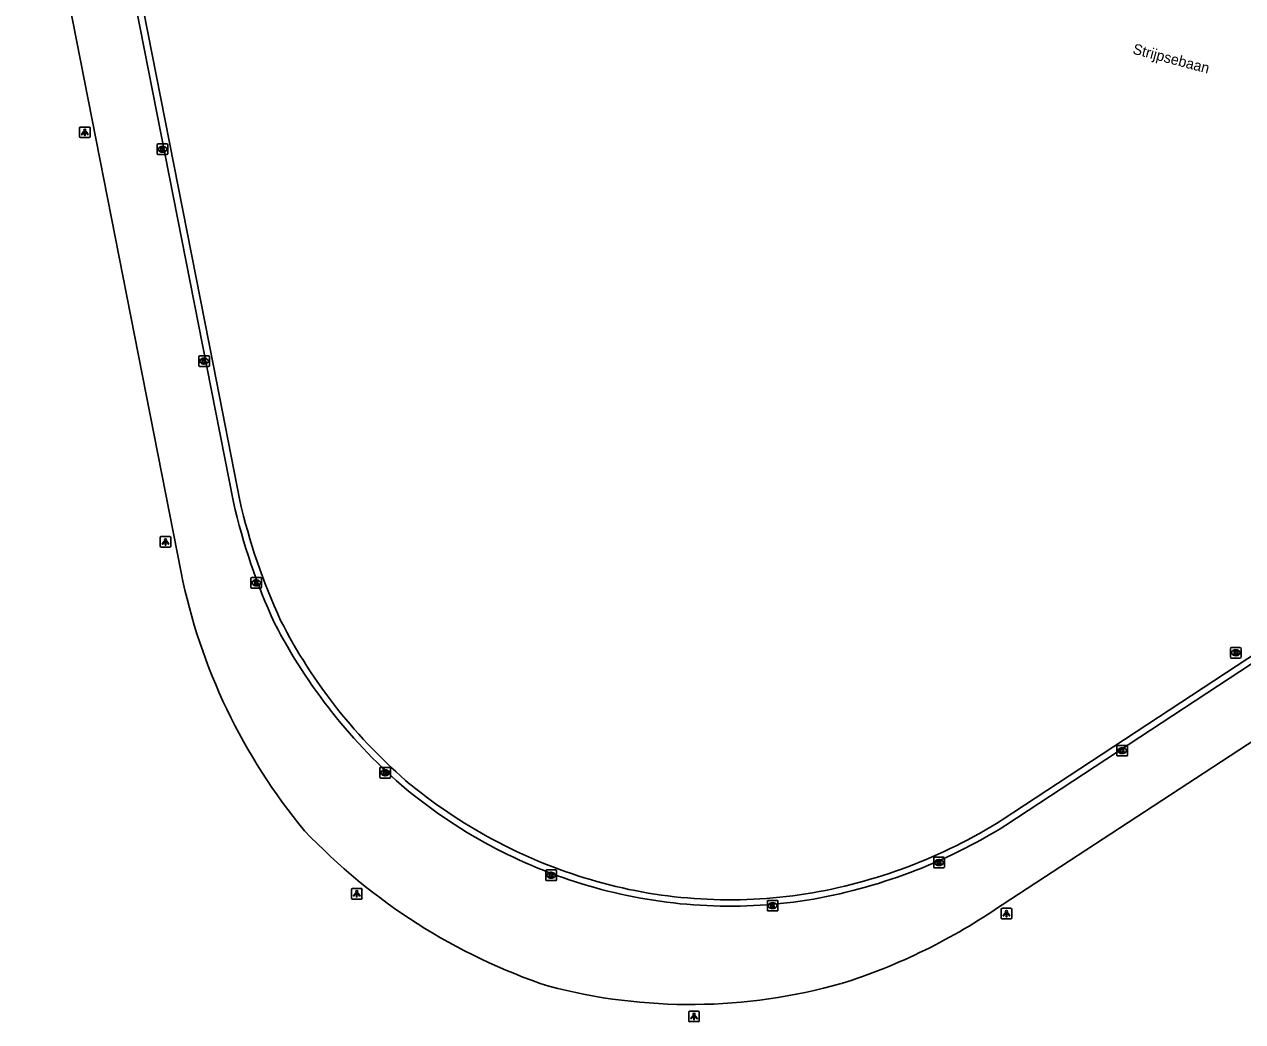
# Model space of a CAD drawing. Extents: x 154324 to 155743, y 382939 to 384183.
# Drawn here: x 154446.7 to 154562, y 382939 to 383033.4 of the extents above; entities that cross this region are included whole.
import ezdxf

# ---------------------------------------------------------------- set-up
doc = ezdxf.new("R2010")
doc.units = 0
for name, color, linetype in [('IMGEO_Brandkraan', 7, 'Continuous'), ('IMGEO_Kolk', 7, 'Continuous'), ('IMGEO_Lichtpunt', 7, 'Continuous'), ('IMGEO_Openbare_ruimte_label', 7, 'Continuous'), ('IMGEO_Rijbaan_lokaal_gesloten', 7, 'Continuous')]:
    doc.layers.add(name, color=color, linetype=linetype)

msp = doc.modelspace()

# ---------------------------------------------------------------- linework, layer by layer
at = {"layer": 'IMGEO_Brandkraan'}
for p, q in [((154560.89, 382973.52), (154560.89, 382974.37)), ((154560.96, 382974.45), (154561.81, 382974.45)), ((154561.81, 382973.45), (154560.96, 382973.45)), ((154561.37, 382974.23), (154561.4, 382974.23)), ((154561.4, 382973.67), (154561.37, 382973.67)), ((154561.89, 382974.37), (154561.89, 382973.52))]:
    msp.add_line(p, q, dxfattribs=at)
for points in [[(154560.89, 382973.52), (154560.89, 382974.37)], [(154560.96, 382974.45), (154561.81, 382974.45)], [(154561.81, 382973.45), (154560.96, 382973.45)], [(154561.23, 382974.15), (154561.23, 382973.75), (154561.45, 382973.75)], [(154561.47, 382974.15), (154561.23, 382974.15)], [(154561.41, 382974.07), (154561.36, 382974.07), (154561.36, 382973.99)], [(154561.36, 382973.99), (154561.41, 382973.99)], [(154561.42, 382973.91), (154561.36, 382973.91), (154561.36, 382973.83)], [(154561.36, 382973.83), (154561.42, 382973.83)], [(154561.89, 382974.37), (154561.89, 382973.52)]]:
    msp.add_lwpolyline(points, dxfattribs=at)
for centre, radius, start, end in [((154560.96, 382974.37), 0.0765, 91.552, 178.448), ((154560.96, 382974.37), 0.0765, 91.552, 178.448), ((154560.96, 382973.52), 0.0765, 181.552, 268.448), ((154560.96, 382973.52), 0.0765, 181.552, 268.448), ((154561.41, 382974.03), 0.0379, 267.8285, 90.9355), ((154561.42, 382973.87), 0.0404, 269.8759, 90.5077), ((154561.45, 382974), 0.251, 268.6676, 293.5347), ((154561.47, 382974), 0.145, 59.4692, 91.5367), ((154561.49, 382974.05), 0.0922, 285.5137, 58.1501), ((154561.5, 382973.86), 0.105, 301.3115, 78.989), ((154561.81, 382974.37), 0.0765, 1.552, 88.448), ((154561.81, 382974.37), 0.0765, 1.552, 88.448), ((154561.81, 382973.52), 0.0765, 271.552, 358.448), ((154561.81, 382973.52), 0.0765, 271.552, 358.448)]:
    msp.add_arc(centre, radius, start, end, dxfattribs=at)
for centre, major_axis, ratio, start_param, end_param in [((154561.37, 382973.95), (-0.387, 0.002), 0.722429, 4.712389, 7.853982), ((154561.4, 382973.95), (-0.39, 0.002), 0.717154, 1.570796, 4.712389)]:
    msp.add_ellipse(centre, major_axis=major_axis, ratio=ratio, start_param=start_param, end_param=end_param, dxfattribs=at)
at = {"layer": 'IMGEO_Kolk'}
for p, q in [((154459.24, 383021.2), (154459.24, 383022.05)), ((154459.31, 383022.12), (154460.17, 383022.12)), ((154459.73, 383021.9), (154459.75, 383021.9)), ((154460.24, 383022.05), (154460.24, 383021.2)), ((154460.17, 383021.12), (154459.31, 383021.12)), ((154459.75, 383021.34), (154459.72, 383021.34)), ((154463.18, 383001.14), (154463.18, 383001.99)), ((154463.26, 383002.06), (154464.11, 383002.06)), ((154464.11, 383001.06), (154463.26, 383001.06)), ((154463.67, 383001.84), (154463.7, 383001.84)), ((154463.69, 383001.28), (154463.67, 383001.28)), ((154464.19, 383001.99), (154464.19, 383001.14)), ((154468.12, 382980.15), (154468.12, 382981)), ((154468.19, 382981.08), (154469.05, 382981.08)), ((154468.63, 382980.3), (154468.6, 382980.3)), ((154468.61, 382980.85), (154468.63, 382980.85)), ((154469.12, 382981), (154469.12, 382980.15)), ((154469.05, 382980.07), (154468.19, 382980.07)), ((154550.12, 382964.25), (154550.12, 382965.11)), ((154550.2, 382965.18), (154551.05, 382965.18)), ((154551.05, 382964.18), (154550.2, 382964.18)), ((154550.61, 382964.96), (154550.63, 382964.96)), ((154550.63, 382964.4), (154550.61, 382964.4)), ((154551.12, 382965.11), (154551.12, 382964.25)), ((154480.32, 382962.17), (154480.32, 382963.02)), ((154480.4, 382963.09), (154481.25, 382963.09)), ((154481.32, 382963.02), (154481.32, 382962.17)), ((154481.25, 382962.09), (154480.4, 382962.09)), ((154480.81, 382962.87), (154480.84, 382962.87)), ((154480.83, 382962.31), (154480.81, 382962.31)), ((154532.78, 382953.66), (154532.78, 382954.52)), ((154532.85, 382954.59), (154533.7, 382954.59)), ((154533.26, 382954.37), (154533.29, 382954.37)), ((154533.29, 382953.81), (154533.26, 382953.81)), ((154533.78, 382954.52), (154533.78, 382953.66)), ((154496.04, 382952.46), (154496.04, 382953.31)), ((154496.12, 382953.39), (154496.97, 382953.39)), ((154496.53, 382953.17), (154496.56, 382953.17)), ((154496.55, 382952.61), (154496.53, 382952.61)), ((154497.04, 382953.31), (154497.04, 382952.46)), ((154533.7, 382953.59), (154532.85, 382953.59)), ((154496.97, 382952.39), (154496.12, 382952.39)), ((154517.02, 382949.58), (154517.02, 382950.43)), ((154517.1, 382950.51), (154517.95, 382950.51)), ((154517.51, 382950.29), (154517.53, 382950.29)), ((154518.02, 382950.43), (154518.02, 382949.58)), ((154517.95, 382949.51), (154517.1, 382949.51)), ((154517.53, 382949.73), (154517.51, 382949.73))]:
    msp.add_line(p, q, dxfattribs=at)
for points in [[(154459.24, 383021.2), (154459.24, 383022.05)], [(154459.31, 383022.12), (154460.17, 383022.12)], [(154459.56, 383021.82), (154459.68, 383021.82), (154459.68, 383021.67), (154459.81, 383021.82), (154459.98, 383021.82), (154459.83, 383021.67), (154459.98, 383021.42), (154459.83, 383021.42), (154459.75, 383021.59), (154459.68, 383021.52), (154459.68, 383021.42), (154459.56, 383021.42), (154459.56, 383021.82)], [(154460.24, 383022.05), (154460.24, 383021.2)], [(154460.17, 383021.12), (154459.31, 383021.12)], [(154463.18, 383001.14), (154463.18, 383001.99)], [(154463.26, 383002.06), (154464.11, 383002.06)], [(154464.11, 383001.06), (154463.26, 383001.06)], [(154463.5, 383001.76), (154463.63, 383001.76), (154463.63, 383001.61), (154463.76, 383001.76), (154463.92, 383001.76), (154463.78, 383001.61), (154463.93, 383001.36), (154463.78, 383001.36), (154463.69, 383001.53), (154463.63, 383001.46), (154463.63, 383001.36), (154463.5, 383001.36), (154463.5, 383001.76)], [(154464.19, 383001.99), (154464.19, 383001.14)], [(154468.12, 382980.15), (154468.12, 382981)], [(154468.19, 382981.08), (154469.05, 382981.08)], [(154468.44, 382980.77), (154468.56, 382980.77), (154468.56, 382980.62), (154468.69, 382980.77), (154468.86, 382980.77), (154468.71, 382980.62), (154468.86, 382980.37), (154468.71, 382980.37), (154468.63, 382980.54), (154468.56, 382980.47), (154468.56, 382980.37), (154468.44, 382980.37), (154468.44, 382980.77)], [(154469.12, 382981), (154469.12, 382980.15)], [(154469.05, 382980.07), (154468.19, 382980.07)], [(154550.12, 382964.25), (154550.12, 382965.11)], [(154550.2, 382965.18), (154551.05, 382965.18)], [(154551.05, 382964.18), (154550.2, 382964.18)], [(154550.44, 382964.88), (154550.57, 382964.88), (154550.57, 382964.73), (154550.69, 382964.88), (154550.86, 382964.88), (154550.71, 382964.73), (154550.87, 382964.48), (154550.71, 382964.48), (154550.63, 382964.64), (154550.57, 382964.58), (154550.57, 382964.48), (154550.44, 382964.48), (154550.44, 382964.88)], [(154551.12, 382965.11), (154551.12, 382964.25)], [(154480.32, 382962.17), (154480.32, 382963.02)], [(154480.4, 382963.09), (154481.25, 382963.09)], [(154481.32, 382963.02), (154481.32, 382962.17)], [(154481.25, 382962.09), (154480.4, 382962.09)], [(154480.64, 382962.79), (154480.77, 382962.79), (154480.77, 382962.64), (154480.9, 382962.79), (154481.06, 382962.79), (154480.91, 382962.64), (154481.07, 382962.39), (154480.91, 382962.39), (154480.83, 382962.56), (154480.77, 382962.49), (154480.77, 382962.39), (154480.64, 382962.39), (154480.64, 382962.79)], [(154532.78, 382953.66), (154532.78, 382954.52)], [(154532.85, 382954.59), (154533.7, 382954.59)], [(154533.1, 382954.29), (154533.22, 382954.29), (154533.22, 382954.14), (154533.35, 382954.29), (154533.51, 382954.29), (154533.37, 382954.14), (154533.52, 382953.89), (154533.37, 382953.89), (154533.28, 382954.06), (154533.22, 382953.99), (154533.22, 382953.89), (154533.1, 382953.89), (154533.1, 382954.29)], [(154533.78, 382954.52), (154533.78, 382953.66)], [(154496.04, 382952.46), (154496.04, 382953.31)], [(154496.12, 382953.39), (154496.97, 382953.39)], [(154496.36, 382953.09), (154496.49, 382953.09), (154496.49, 382952.94), (154496.62, 382953.09), (154496.78, 382953.09), (154496.63, 382952.94), (154496.79, 382952.69), (154496.63, 382952.69), (154496.55, 382952.85), (154496.49, 382952.79), (154496.49, 382952.69), (154496.36, 382952.69), (154496.36, 382953.09)], [(154497.04, 382953.31), (154497.04, 382952.46)], [(154533.7, 382953.59), (154532.85, 382953.59)], [(154496.97, 382952.39), (154496.12, 382952.39)], [(154517.02, 382949.58), (154517.02, 382950.43)], [(154517.1, 382950.51), (154517.95, 382950.51)], [(154518.02, 382950.43), (154518.02, 382949.58)], [(154517.95, 382949.51), (154517.1, 382949.51)], [(154517.34, 382950.21), (154517.47, 382950.21), (154517.47, 382950.05), (154517.59, 382950.21), (154517.76, 382950.21), (154517.61, 382950.06), (154517.77, 382949.81), (154517.61, 382949.81), (154517.53, 382949.97), (154517.47, 382949.9), (154517.47, 382949.81), (154517.34, 382949.81), (154517.34, 382950.21)]]:
    msp.add_lwpolyline(points, dxfattribs=at)
for centre, start, end in [((154459.31, 383022.05), 91.552, 178.448), ((154459.31, 383022.05), 91.552, 178.448), ((154460.16, 383022.05), 1.552, 88.448), ((154460.16, 383022.05), 1.552, 88.448), ((154459.31, 383021.2), 181.552, 268.448), ((154459.31, 383021.2), 181.552, 268.448), ((154460.16, 383021.2), 271.552, 358.448), ((154460.16, 383021.2), 271.552, 358.448), ((154463.26, 383001.99), 91.552, 178.448), ((154463.26, 383001.99), 91.552, 178.448), ((154463.26, 383001.14), 181.552, 268.448), ((154463.26, 383001.14), 181.552, 268.448), ((154464.11, 383001.99), 1.552, 88.448), ((154464.11, 383001.99), 1.552, 88.448), ((154464.11, 383001.14), 271.552, 358.448), ((154464.11, 383001.14), 271.552, 358.448), ((154468.19, 382981), 91.552, 178.448), ((154468.19, 382981), 91.552, 178.448), ((154469.04, 382981), 1.552, 88.448), ((154469.04, 382981), 1.552, 88.448), ((154468.19, 382980.15), 181.552, 268.448), ((154468.19, 382980.15), 181.552, 268.448), ((154469.04, 382980.15), 271.552, 358.448), ((154469.04, 382980.15), 271.552, 358.448), ((154550.2, 382965.1), 91.552, 178.448), ((154550.2, 382965.1), 91.552, 178.448), ((154550.2, 382964.26), 181.552, 268.448), ((154550.2, 382964.26), 181.552, 268.448), ((154551.05, 382965.1), 1.552, 88.448), ((154551.05, 382965.1), 1.552, 88.448), ((154551.05, 382964.26), 271.552, 358.448), ((154551.05, 382964.26), 271.552, 358.448), ((154480.4, 382963.02), 91.552, 178.448), ((154480.4, 382963.02), 91.552, 178.448), ((154481.25, 382963.02), 1.552, 88.448), ((154481.25, 382963.02), 1.552, 88.448), ((154480.4, 382962.17), 181.552, 268.448), ((154480.4, 382962.17), 181.552, 268.448), ((154481.25, 382962.17), 271.552, 358.448), ((154481.25, 382962.17), 271.552, 358.448), ((154532.85, 382954.52), 91.552, 178.448), ((154532.85, 382954.52), 91.552, 178.448), ((154533.7, 382954.52), 1.552, 88.448), ((154533.7, 382954.52), 1.552, 88.448), ((154496.12, 382953.31), 91.552, 178.448), ((154496.12, 382953.31), 91.552, 178.448), ((154496.97, 382953.31), 1.552, 88.448), ((154496.97, 382953.31), 1.552, 88.448), ((154532.85, 382953.67), 181.552, 268.448), ((154532.85, 382953.67), 181.552, 268.448), ((154533.7, 382953.67), 271.552, 358.448), ((154533.7, 382953.67), 271.552, 358.448), ((154496.12, 382952.46), 181.552, 268.448), ((154496.12, 382952.46), 181.552, 268.448), ((154496.97, 382952.46), 271.552, 358.448), ((154496.97, 382952.46), 271.552, 358.448), ((154517.1, 382950.43), 91.552, 178.448), ((154517.1, 382950.43), 91.552, 178.448), ((154517.95, 382950.43), 1.552, 88.448), ((154517.95, 382950.43), 1.552, 88.448), ((154517.1, 382949.58), 181.552, 268.448), ((154517.1, 382949.58), 181.552, 268.448), ((154517.95, 382949.58), 271.552, 358.448), ((154517.95, 382949.58), 271.552, 358.448)]:
    msp.add_arc(centre, 0.0765, start, end, dxfattribs=at)
for centre, major_axis, ratio, start_param, end_param in [((154459.73, 383021.62), (-0.387, 0.002), 0.722429, 4.712389, 7.853982), ((154459.75, 383021.62), (-0.39, 0.002), 0.717154, 1.570796, 4.712389), ((154463.67, 383001.56), (-0.387, 0.002), 0.722429, 4.712389, 7.853982), ((154463.7, 383001.56), (-0.39, 0.002), 0.717154, 1.570796, 4.712389), ((154468.61, 382980.57), (-0.387, 0.002), 0.722429, 4.712389, 7.853982), ((154468.63, 382980.57), (-0.39, 0.002), 0.717154, 1.570796, 4.712389), ((154550.61, 382964.68), (-0.387, 0.002), 0.722429, 4.712389, 7.853982), ((154550.63, 382964.68), (-0.39, 0.002), 0.717154, 1.570796, 4.712389), ((154480.81, 382962.59), (-0.387, 0.002), 0.722429, 4.712389, 7.853982), ((154480.83, 382962.59), (-0.39, 0.002), 0.717154, 1.570796, 4.712389), ((154533.26, 382954.09), (-0.387, 0.002), 0.722429, 4.712389, 7.853982), ((154533.29, 382954.09), (-0.39, 0.002), 0.717154, 1.570796, 4.712389), ((154496.53, 382952.89), (-0.387, 0.002), 0.722429, 4.712389, 7.853982), ((154496.55, 382952.89), (-0.39, 0.002), 0.717154, 1.570796, 4.712389), ((154517.51, 382950.01), (-0.387, 0.002), 0.722429, 4.712389, 7.853982), ((154517.53, 382950.01), (-0.39, 0.002), 0.717154, 1.570796, 4.712389)]:
    msp.add_ellipse(centre, major_axis=major_axis, ratio=ratio, start_param=start_param, end_param=end_param, dxfattribs=at)
at = {"layer": 'IMGEO_Lichtpunt'}
for p, q in [((154451.89, 383023.63), (154451.89, 383022.82)), ((154451.89, 383023.63), (154451.89, 383022.82)), ((154452.79, 383023.72), (154451.99, 383023.72)), ((154452.79, 383023.72), (154451.99, 383023.72)), ((154452.89, 383022.82), (154452.89, 383023.63)), ((154452.89, 383022.82), (154452.89, 383023.63)), ((154451.99, 383022.73), (154452.79, 383022.73)), ((154451.99, 383022.73), (154452.79, 383022.73)), ((154460.43, 382984.95), (154459.63, 382984.95)), ((154460.43, 382984.95), (154459.63, 382984.95)), ((154459.53, 382984.86), (154459.53, 382984.05)), ((154459.53, 382984.86), (154459.53, 382984.05)), ((154459.63, 382983.95), (154460.43, 382983.95)), ((154459.63, 382983.95), (154460.43, 382983.95)), ((154460.53, 382984.05), (154460.53, 382984.86)), ((154460.53, 382984.05), (154460.53, 382984.86)), ((154477.64, 382951.53), (154477.64, 382950.73)), ((154477.64, 382951.53), (154477.64, 382950.73)), ((154478.54, 382951.63), (154477.73, 382951.63)), ((154478.54, 382951.63), (154477.73, 382951.63)), ((154478.63, 382950.73), (154478.63, 382951.53)), ((154478.63, 382950.73), (154478.63, 382951.53)), ((154477.73, 382950.63), (154478.54, 382950.63)), ((154477.73, 382950.63), (154478.54, 382950.63)), ((154539.17, 382949.66), (154539.17, 382948.85)), ((154539.17, 382949.66), (154539.17, 382948.85)), ((154540.07, 382949.76), (154539.26, 382949.76)), ((154540.07, 382949.76), (154539.26, 382949.76)), ((154540.16, 382948.85), (154540.16, 382949.66)), ((154540.16, 382948.85), (154540.16, 382949.66)), ((154539.26, 382948.76), (154540.07, 382948.76)), ((154539.26, 382948.76), (154540.07, 382948.76)), ((154509.58, 382939.93), (154509.58, 382939.12)), ((154509.58, 382939.93), (154509.58, 382939.12)), ((154510.48, 382940.03), (154509.67, 382940.03)), ((154510.48, 382940.03), (154509.67, 382940.03)), ((154510.57, 382939.12), (154510.57, 382939.93)), ((154510.57, 382939.12), (154510.57, 382939.93)), ((154509.67, 382939.03), (154510.48, 382939.03)), ((154509.67, 382939.03), (154510.48, 382939.03))]:
    msp.add_line(p, q, dxfattribs=at)
for points in [[(154452.27, 383023.29), (154452.3, 383023.26), (154452.12, 383023), (154452.08, 383023.03), (154452.27, 383023.29)], [(154452.37, 383023.24), (154452.41, 383023.24), (154452.41, 383022.92), (154452.37, 383022.92), (154452.37, 383023.24)], [(154452.48, 383023.26), (154452.52, 383023.29), (154452.7, 383023.03), (154452.66, 383023), (154452.48, 383023.26)], [(154459.91, 382984.52), (154459.94, 382984.49), (154459.76, 382984.23), (154459.72, 382984.26), (154459.91, 382984.52)], [(154460.01, 382984.47), (154460.06, 382984.47), (154460.06, 382984.15), (154460.01, 382984.15), (154460.01, 382984.47)], [(154460.12, 382984.49), (154460.16, 382984.52), (154460.34, 382984.26), (154460.3, 382984.23), (154460.12, 382984.49)], [(154478.01, 382951.2), (154478.05, 382951.17), (154477.86, 382950.91), (154477.82, 382950.94), (154478.01, 382951.2)], [(154478.11, 382951.15), (154478.16, 382951.15), (154478.16, 382950.83), (154478.11, 382950.83), (154478.11, 382951.15)], [(154478.22, 382951.17), (154478.26, 382951.2), (154478.45, 382950.93), (154478.41, 382950.91), (154478.22, 382951.17)], [(154539.54, 382949.32), (154539.58, 382949.3), (154539.39, 382949.03), (154539.35, 382949.06), (154539.54, 382949.32)], [(154539.64, 382949.28), (154539.69, 382949.28), (154539.69, 382948.95), (154539.64, 382948.95), (154539.64, 382949.28)], [(154539.75, 382949.3), (154539.79, 382949.32), (154539.98, 382949.06), (154539.94, 382949.03), (154539.75, 382949.3)], [(154509.95, 382939.59), (154509.99, 382939.57), (154509.8, 382939.3), (154509.76, 382939.33), (154509.95, 382939.59)], [(154510.05, 382939.55), (154510.1, 382939.55), (154510.1, 382939.22), (154510.05, 382939.22), (154510.05, 382939.55)], [(154510.16, 382939.57), (154510.2, 382939.59), (154510.39, 382939.33), (154510.35, 382939.3), (154510.16, 382939.57)]]:
    msp.add_lwpolyline(points, dxfattribs=at)
for centre in [(154452.39, 383023.43), (154460.03, 382984.65), (154478.14, 382951.33), (154539.67, 382949.46), (154510.08, 382939.73)]:
    msp.add_circle(centre, 0.0994, dxfattribs=at)
for centre, start, end in [((154451.99, 383023.63), 90, 180), ((154451.99, 383023.63), 90, 180), ((154452.79, 383023.63), 0, 90), ((154452.79, 383023.63), 0, 90), ((154451.99, 383022.82), 180, 270), ((154451.99, 383022.82), 180, 270), ((154452.79, 383022.82), 270, 0), ((154452.79, 383022.82), 270, 360), ((154459.63, 382984.86), 90, 180), ((154459.63, 382984.86), 90, 180), ((154460.43, 382984.86), 0, 90), ((154460.43, 382984.86), 0, 90), ((154459.63, 382984.05), 180, 270), ((154459.63, 382984.05), 180, 270), ((154460.43, 382984.05), 270, 0), ((154460.43, 382984.05), 270, 360), ((154477.73, 382951.53), 90, 180), ((154477.73, 382951.53), 90, 180), ((154478.54, 382951.53), 0, 90), ((154478.54, 382951.53), 0, 90), ((154477.73, 382950.73), 180, 270), ((154477.73, 382950.73), 180, 270), ((154478.54, 382950.73), 270, 0), ((154478.54, 382950.73), 270, 360), ((154539.26, 382949.66), 90, 180), ((154539.26, 382949.66), 90, 180), ((154540.07, 382949.66), 0, 90), ((154540.07, 382949.66), 0, 90), ((154539.26, 382948.85), 180, 270), ((154539.26, 382948.85), 180, 270), ((154540.07, 382948.85), 270, 0), ((154540.07, 382948.85), 270, 360), ((154509.67, 382939.93), 90, 180), ((154509.67, 382939.93), 90, 180), ((154510.48, 382939.93), 0, 90), ((154510.48, 382939.93), 0, 90), ((154509.67, 382939.12), 180, 270), ((154509.67, 382939.12), 180, 270), ((154510.48, 382939.12), 270, 0), ((154510.48, 382939.12), 270, 360)]:
    msp.add_arc(centre, 0.0946, start, end, dxfattribs=at)
at = {"layer": 'IMGEO_Rijbaan_lokaal_gesloten'}
for points in [[(154461.51, 382981.55), (154450.87, 383035.65), (154439.15, 383095.25), (154422.31, 383181.22), (154406.72, 383260.28), (154396.48, 383312.17), (154394.42, 383322.32), (154392.95, 383329.96)], [(154466.46, 382988.22), (154463.94, 383001.02), (154453.69, 383053.15), (154432.24, 383162.26), (154411.51, 383267.43), (154400.66, 383322.48)], [(154415.36, 383251.02), (154421.4, 383220.37), (154444.99, 383100.45), (154464.56, 383001.13), (154467.07, 382988.36)], [(154539.25, 382958.13), (154607.95, 383003.23)], [(154608.29, 383002.71), (154539.6, 382957.62)], [(154607.05, 382994.38), (154553.54, 382959.42), (154539.25, 382950.1)]]:
    msp.add_lwpolyline(points, dxfattribs=at)
for centre, radius, start, end in [((154523.54, 383001.26), 57.93, 192.8711, 204.7457), ((154522.78, 383000.96), 57.74, 192.7495, 204.7878), ((154515.59, 382992.4), 55.16, 191.3377, 219.7864), ((154515.81, 382999.9), 50.38, 207.0226, 229.7267), ((154516.28, 383000.38), 51.64, 207.2284, 229.6764), ((154513.68, 382998.4), 48.46, 230.5036, 254.4383), ((154514.19, 382999.44), 48.99, 230.8269, 254.2103), ((154512.69, 383000.44), 49.96, 279.1993, 302.1275), ((154512.32, 383001.51), 51.68, 279.3989, 301.8697), ((154514.24, 382996.02), 56.56, 223.4828, 251.5325), ((154513.49, 382997.42), 47.46, 254.3399, 278.801), ((154513.49, 382997.32), 46.76, 254.3311, 278.8421), ((154506.9, 382996.74), 56.76, 287.5622, 304.7459), ((154509.71, 382993.24), 52.59, 255.2615, 285.7936)]:
    msp.add_arc(centre, radius, start, end, dxfattribs=at)

# ---------------------------------------------------------------- texts
at = {"layer": 'IMGEO_Openbare_ruimte_label'}
msp.add_text('Strijpsebaan', height=1, rotation=345.1719, dxfattribs=at).set_placement((154551.55, 383030.68))

doc.saveas('drawing.dxf')
